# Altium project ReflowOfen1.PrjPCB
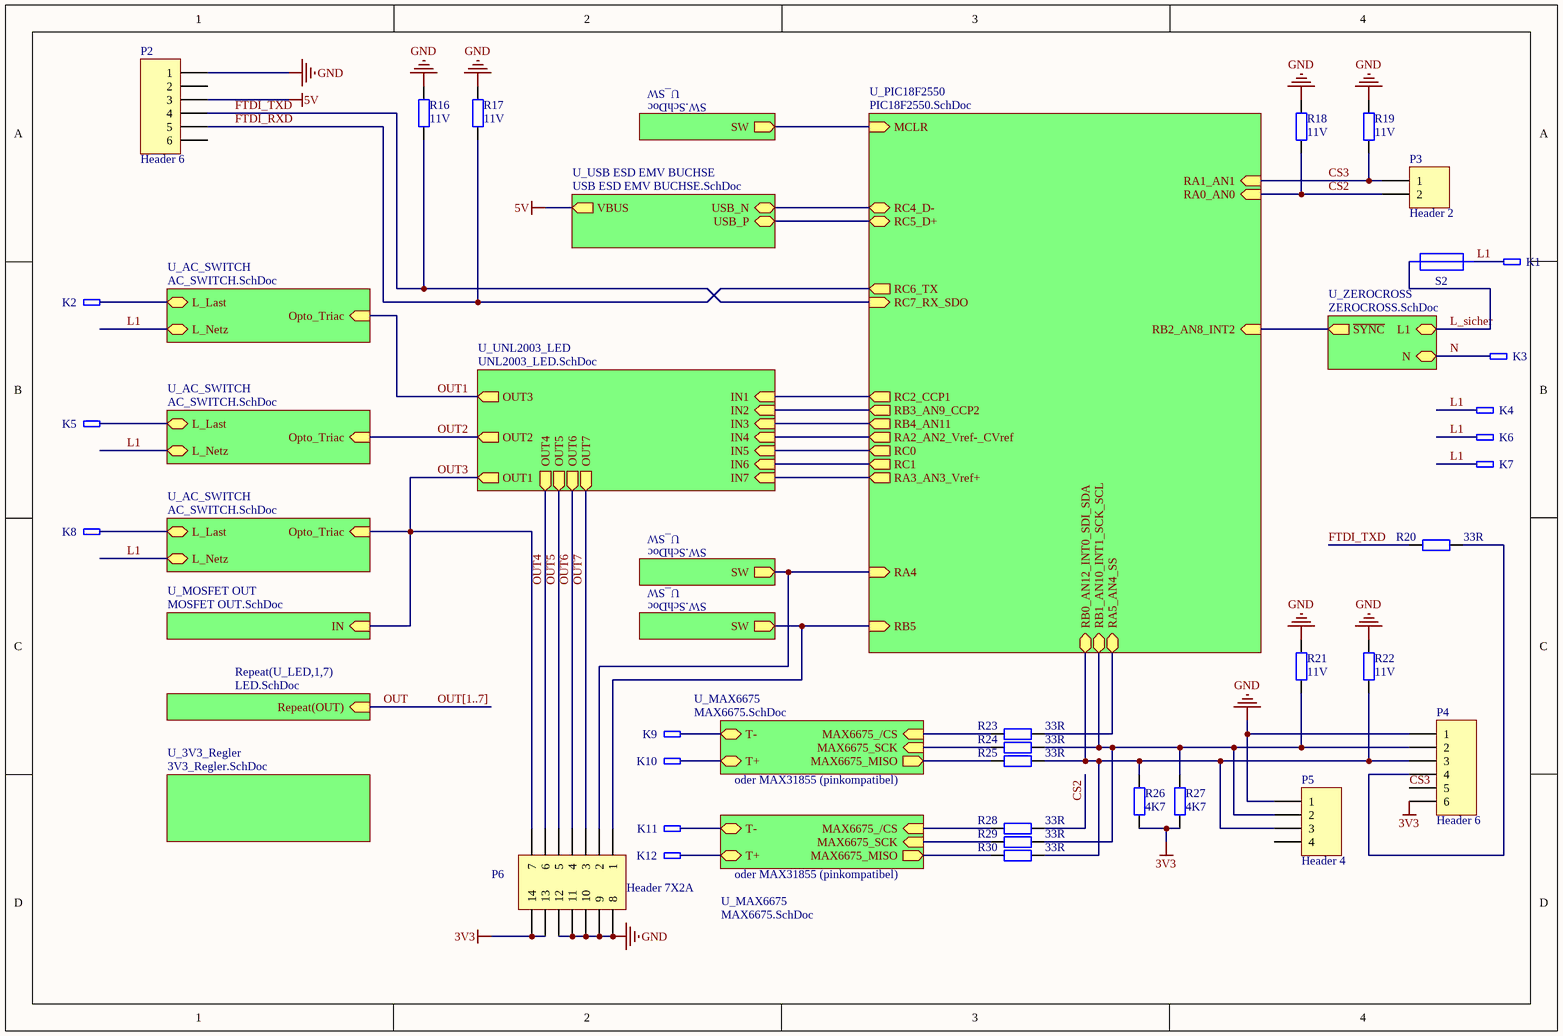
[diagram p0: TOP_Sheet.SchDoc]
11 sheets, 137 parts. Net scope: hierarchical (ports join the sheet entries above them; power ports are global).
Board file: Reflow_1.0.PcbDoc
Sheets:
  TOP_Sheet.SchDoc
    U_3V3_Regler = 3V3_Regler.SchDoc
    U_PIC18F2550 = PIC18F2550.SchDoc
    U_ZEROCROSS = ZEROCROSS.SchDoc
    U_SW = SW.SchDoc
    U_LED1 = LED.SchDoc
    U_LED2 = LED.SchDoc
    U_LED3 = LED.SchDoc
    U_LED4 = LED.SchDoc
    U_LED5 = LED.SchDoc
    U_LED6 = LED.SchDoc
    U_LED7 = LED.SchDoc
    U_MAX6675 = MAX6675.SchDoc
    U_AC_SWITCH = AC_SWITCH.SchDoc
    U_AC_SWITCH = AC_SWITCH.SchDoc
    U_AC_SWITCH = AC_SWITCH.SchDoc
    U_SW = SW.SchDoc
    U_UNL2003_LED = UNL2003_LED.SchDoc
    U_MOSFET OUT = MOSFET OUT.SchDoc
    U_SW = SW.SchDoc
    U_USB ESD EMV BUCHSE = USB ESD EMV BUCHSE.SchDoc
    U_MAX6675 = MAX6675.SchDoc

## Sheet TOP_Sheet.SchDoc
size A4; DocumentNumber: 1; SheetNumber: 1; SheetTotal: 11; Abteilung: Hard/Software Entwicklung

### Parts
K1  WAGO-236  [KL02X196Y0A0]  (value not drawn)
K2  WAGO-236  [KL02X196Y0A0]  (value not drawn)
K3  WAGO-236  [KL02X196Y0A0]  (value not drawn)
K4  WAGO-236  [KL02X196Y0A0]  (value not drawn)
K5  WAGO-236  [KL02X196Y0A0]  (value not drawn)
K6  WAGO-236  [KL02X196Y0A0]  (value not drawn)
K7  WAGO-236  [KL02X196Y0A0]  (value not drawn)
K8  WAGO-236  [KL02X196Y0A0]  (value not drawn)
K9  WAGO-233  [KL02X0Y197A0]  (value not drawn)
K10  WAGO-233  [KL02X0Y197A0]  (value not drawn)
K11  WAGO-233  [KL02X0Y197A0]  (value not drawn)
K12  WAGO-233  [KL02X0Y197A0]  (value not drawn)
P2  Header 6  [HDR1X6]
P3  Header 2  [HDR1X2]
P4  Header 6  [HDR1X6]
P5  Header 4  [HDR1X4]
P6  Header 7X2A  [HDR2X7_CEN]
R16  11V  [RLCDT_1206]
R17  11V  [RLCDT_1206]
R18  11V  [RLCDT_1206]
R19  11V  [RLCDT_1206]
R20  33R  [RLCDT_1206]
R21  11V  [RLCDT_1206]
R22  11V  [RLCDT_1206]
R23  33R  [RLCDT_1206]
R24  33R  [RLCDT_1206]
R25  33R  [RLCDT_1206]
R26  4K7  [RLCDT_1206]
R27  4K7  [RLCDT_1206]
R28  33R  [RLCDT_1206]
R29  33R  [RLCDT_1206]
R30  33R  [RLCDT_1206]
S2  SICHERUNGSHALTER_MIRA  [SICHERUNGSHALTER_MIRA]  (value not drawn)

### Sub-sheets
Repeat(U_LED,1,7) = LED.SchDoc: Repeat(OUT) (in)
U_3V3_Regler = 3V3_Regler.SchDoc: no entries
U_AC_SWITCH = AC_SWITCH.SchDoc: L_Netz (bidir), L_Last (bidir), Opto_Triac (in)
U_AC_SWITCH = AC_SWITCH.SchDoc: L_Netz (bidir), L_Last (bidir), Opto_Triac (in)
U_AC_SWITCH = AC_SWITCH.SchDoc: L_Netz (bidir), L_Last (bidir), Opto_Triac (in)
U_MAX6675 = MAX6675.SchDoc: MAX6675_MISO (out), MAX6675_/CS (in), MAX6675_SCK (in), T+ (bidir), T- (bidir)
U_MAX6675 = MAX6675.SchDoc: MAX6675_MISO (out), MAX6675_/CS (in), MAX6675_SCK (in), T+ (bidir), T- (bidir)
U_MOSFET OUT = MOSFET OUT.SchDoc: IN (in)
U_PIC18F2550 = PIC18F2550.SchDoc: MCLR (in), RA0_AN0 (in), RA1_AN1 (in), RA2_AN2_Vref-_CVref (out), RA3_AN3_Vref+ (out), RA4 (in), RA5_AN4_SS (bidir), RB0_AN12_INT0_SDI_SDA (bidir), RB1_AN10_INT1_SCK_SCL (bidir), RB2_AN8_INT2 (in), RB3_AN9_CCP2 (out), RB4_AN11 (out), RB5 (in), RC0 (out), RC1 (out), RC2_CCP1 (out), RC4_D- (bidir), RC5_D+ (bidir), RC6_TX (out), RC7_RX_SDO (in)
U_SW = SW.SchDoc: SW (out)
U_SW = SW.SchDoc: SW (out)
U_SW = SW.SchDoc: SW (out)
U_UNL2003_LED = UNL2003_LED.SchDoc: IN7 (in), IN6 (in), IN5 (in), IN4 (in), OUT1 (out), OUT2 (out), OUT3 (out), IN1 (in), IN2 (in), IN3 (in), OUT4 (out), OUT5 (out), OUT6 (out), OUT7 (out)
U_USB ESD EMV BUCHSE = USB ESD EMV BUCHSE.SchDoc: USB_N (bidir), USB_P (bidir), VBUS (out)
U_ZEROCROSS = ZEROCROSS.SchDoc: ~{SYNC} (out), L1 (bidir), N (bidir)

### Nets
3V3: P4.6 P6.13 P6.14 R26.2 R27.2
5V: P2.3 ; sheet U_USB ESD EMV BUCHSE/VBUS  [project net VBUS]
GND: P2.1 P4.1 P5.1 P6.8 P6.9 P6.10 P6.11 P6.12 R16.1 R17.1 R18.1 R19.1 R21.1 R22.1
~{SYNC}: sheet U_PIC18F2550/RB2_AN8_INT2, sheet U_ZEROCROSS/~{SYNC}
CS2: P3.2 R18.2 R28.1 ; sheet U_PIC18F2550/RA0_AN0
CS3: P3.1 P4.5 R19.2 ; sheet U_PIC18F2550/RA1_AN1
FTDI_RXD: P2.5 R17.2 ; sheet U_PIC18F2550/RC6_TX
FTDI_TXD: P2.4 R16.2 R20.2 ; sheet U_PIC18F2550/RC7_RX_SDO
L1: K1.1 K4.1 K6.1 K7.1 S2.1 ; sheet U_AC_SWITCH/L_Netz, sheet U_AC_SWITCH/L_Netz, sheet U_AC_SWITCH/L_Netz
L_sicher: S2.4 ; sheet U_ZEROCROSS/L1
MCLR: sheet U_PIC18F2550/MCLR, sheet U_SW/SW
N: K3.1 ; sheet U_ZEROCROSS/N
OUT1: sheet U_AC_SWITCH/Opto_Triac, sheet U_UNL2003_LED/OUT3
OUT2: sheet U_AC_SWITCH/Opto_Triac, sheet U_UNL2003_LED/OUT2
OUT3: P6.7 ; sheet U_AC_SWITCH/Opto_Triac, sheet U_UNL2003_LED/OUT1, sheet U_MOSFET OUT/IN
OUT4: P6.6 ; sheet U_UNL2003_LED/OUT4
OUT5: P6.5 ; sheet U_UNL2003_LED/OUT5
OUT6: P6.4 ; sheet U_UNL2003_LED/OUT6
OUT7: P6.3 ; sheet U_UNL2003_LED/OUT7
USB_N: sheet U_PIC18F2550/RC4_D-, sheet U_USB ESD EMV BUCHSE/USB_N
USB_P: sheet U_PIC18F2550/RC5_D+, sheet U_USB ESD EMV BUCHSE/USB_P
Net*1A_1: K8.1 ; sheet U_AC_SWITCH/L_Last
Net*1B_1: K2.1 ; sheet U_AC_SWITCH/L_Last
Net*1C_1: K5.1 ; sheet U_AC_SWITCH/L_Last
NetC9A_1: K12.1 ; sheet U_MAX6675/T+
NetC9A_2: K11.1 ; sheet U_MAX6675/T-
NetC9B_1: K10.1 ; sheet U_MAX6675/T+
NetC9B_2: K9.1 ; sheet U_MAX6675/T-
NetIC3A_5: R29.2 ; sheet U_MAX6675/MAX6675_SCK
NetIC3A_6: R28.2 ; sheet U_MAX6675/MAX6675_/CS
NetIC3A_7: R30.2 ; sheet U_MAX6675/MAX6675_MISO
NetIC3B_5: R24.2 ; sheet U_MAX6675/MAX6675_SCK
NetIC3B_6: R23.2 ; sheet U_MAX6675/MAX6675_/CS
NetIC3B_7: R25.2 ; sheet U_MAX6675/MAX6675_MISO
NetIC4_1: sheet U_PIC18F2550/RA3_AN3_Vref+, sheet U_UNL2003_LED/IN7
NetIC4_2: sheet U_PIC18F2550/RC1, sheet U_UNL2003_LED/IN6
NetIC4_3: sheet U_PIC18F2550/RC0, sheet U_UNL2003_LED/IN5
NetIC4_4: sheet U_PIC18F2550/RA2_AN2_Vref-_CVref, sheet U_UNL2003_LED/IN4
NetIC4_5: sheet U_PIC18F2550/RC2_CCP1, sheet U_UNL2003_LED/IN1
NetIC4_6: sheet U_PIC18F2550/RB3_AN9_CCP2, sheet U_UNL2003_LED/IN2
NetIC4_7: sheet U_PIC18F2550/RB4_AN11, sheet U_UNL2003_LED/IN3
NetP4_2: P4.2 P5.2 R21.2 R24.1 R27.1 R29.1 ; sheet U_PIC18F2550/RB1_AN10_INT1_SCK_SCL
NetP4_3: P4.3 P5.3 R22.2 R25.1 R26.1 R30.1 ; sheet U_PIC18F2550/RB0_AN12_INT0_SDI_SDA
NetP4_4: P4.4 R20.1
NetP6_1: P6.1 ; sheet U_PIC18F2550/RB5, sheet U_SW/SW
NetP6_2: P6.2 ; sheet U_PIC18F2550/RA4, sheet U_SW/SW
NetR23_1: R23.1 ; sheet U_PIC18F2550/RA5_AN4_SS

Not connected (* = marked no-connect by the designer): P2 2 6; P5 4

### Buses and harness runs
bus OUT[1..7]

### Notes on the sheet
- oder MAX31855 (pinkompatibel)

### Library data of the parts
K1-K8 = WAGO-236: CAGE CLAMP RM5 WAGO236 SERIES; D_Hersteller: WAGO; E_Herstellerbezeichnung: 236
K9-K12 = WAGO-233: CAGE CLAMP RM2.5; B_Bestellnummer: 804769; D_Hersteller: WAGO; E_Herstellerbezeichnung: 233
P2 P4 = Header 6: Header, 6-Pin
P3 = Header 2: Header, 2-Pin
P5 = Header 4: Header, 4-Pin
P6 = Header 7X2A: Header, 7-Pin, Dual row
R16-R19 R21 R22 = R: Widerstand; D_Hersteller: WUERTH; E_Herstellerbezeichnung: 825 41 110
R20 R23-R30 = R: Widerstand
S2 = SICHERUNGSHALTER_MIRA: FUSEHOLDER; B_Bestellnummer: 7851/6

## Sheet 3V3_Regler.SchDoc
size A4; DocumentNumber: 2; SheetNumber: 2; SheetTotal: 11; PageSetup: Record=PageOptions|CenterHorizontal=True|CenterVertical=True|PrintScale=0.70|XCorrection=1.00|YCorrection=1.00|PrintKind=0|BorderSize=5000000|LeftOffset=5|BottomOffset=0|Orientation=1|PaperLength=1000|PaperWidth=1000|Scale=100|PaperSource=7|PrintQuality=-4|MediaType=1|DitherType=10|PaperKind=A4|PrintScaleMode=1; Abteilung: Hard/Software Entwicklung
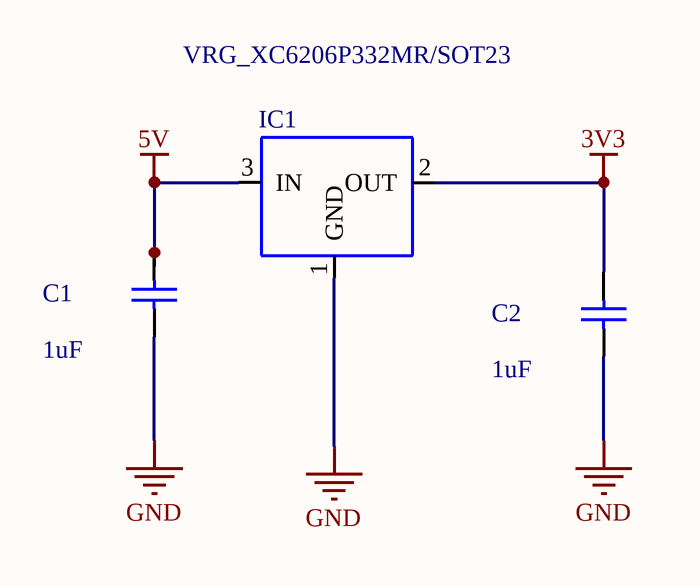
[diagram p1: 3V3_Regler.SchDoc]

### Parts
C1  1uF  [RLCDT_1206]
C2  1uF  [RLCDT_1206]
IC1  VRG_XC6206P332MR/SOT23  [RLCDT_SOT23]

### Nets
3V3: C2.1 IC1.2(OUT)
5V: C1.1 IC1.3(IN)  [project net VBUS]
GND: C1.2 C2.2 IC1.1(GND)

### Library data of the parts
C1 C2 = C_KERAMIK: Kondensator, Keramik
IC1 = VRG_XC6206P332MR/SOT23: VOLTAGE REGULATOR 3V3 250mA; B_Bestellnummer: 58796980; D_Hersteller: TOREX

## Sheet PIC18F2550.SchDoc
size A4; DocumentNumber: 3; SheetNumber: 3; SheetTotal: 11; Abteilung: Hard/Software Entwicklung
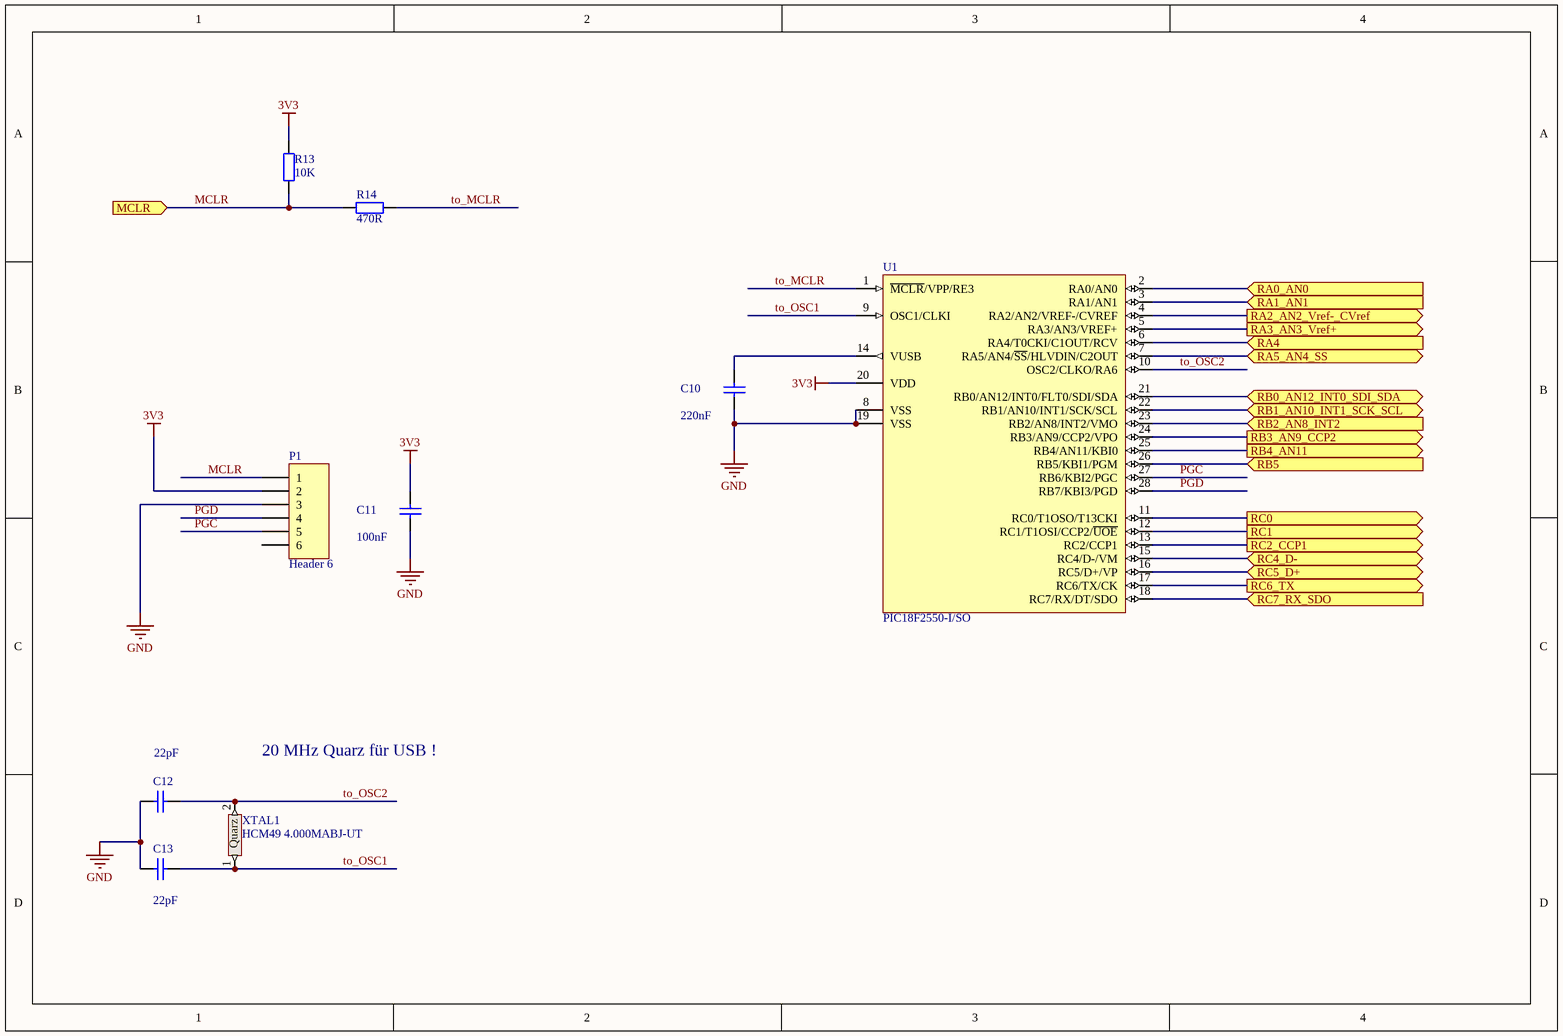
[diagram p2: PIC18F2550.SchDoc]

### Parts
C10  220nF  [RLCDT_1206]
C11  100nF  [RLCDT_1206]
C12  22pF  [RLCDT_1206]
C13  22pF  [RLCDT_1206]
P1  Header 6  [HDR1X6]
R13  10K  [RLCDT_1206]
R14  470R  [RLCDT_1206]
U1  PIC18F2550-I/SO  [SOIC-SO28_N]
XTAL1  HCM49 4.000MABJ-UT  [IC_M-HCM49]

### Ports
MCLR (in), RA0_AN0 (in), RA1_AN1 (in), RA2_AN2_Vref-_CVref (out), RA3_AN3_Vref+ (out), RA4 (in), RA5_AN4_SS (bidir), RB0_AN12_INT0_SDI_SDA (bidir), RB1_AN10_INT1_SCK_SCL (bidir), RB2_AN8_INT2 (in), RB3_AN9_CCP2 (out), RB4_AN11 (out), RB5 (in), RC0 (out), RC1 (out), RC2_CCP1 (out), RC4_D- (bidir), RC5_D+ (bidir), RC6_TX (out), RC7_RX_SDO (in)

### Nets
3V3: C11.1 P1.2 R13.2 U1.20(VDD)
GND: C10.2 C11.2 C12.1 C13.1 P1.3 U1.8(VSS) U1.19(VSS)
~{SYNC}: U1.23(RB2/AN8/INT2/VMO) ; port RB2_AN8_INT2
CS2: U1.2(RA0/AN0) ; port RA0_AN0
CS3: U1.3(RA1/AN1) ; port RA1_AN1
FTDI_RXD: U1.17(RC6/TX/CK) ; port RC6_TX
FTDI_TXD: U1.18(RC7/RX/DT/SDO) ; port RC7_RX_SDO
MCLR: P1.1 R13.1 R14.2 ; port MCLR
PGC: P1.5 U1.27(RB6/KBI2/PGC)
PGD: P1.4 U1.28(RB7/KBI3/PGD)
to_MCLR: R14.1 U1.1(~{MCLR}/VPP/RE3)
to_OSC1: C13.2 U1.9(OSC1/CLKI) XTAL1.1
to_OSC2: C12.2 U1.10(OSC2/CLKO/RA6) XTAL1.2
USB_N: U1.15(RC4/D-/VM) ; port RC4_D-
USB_P: U1.16(RC5/D+/VP) ; port RC5_D+
NetC10_1: C10.1 U1.14(VUSB)
NetIC4_1: U1.5(RA3/AN3/VREF+) ; port RA3_AN3_Vref+
NetIC4_2: U1.12(RC1/T1OSI/CCP2/~{UOE}) ; port RC1
NetIC4_3: U1.11(RC0/T1OSO/T13CKI) ; port RC0
NetIC4_4: U1.4(RA2/AN2/VREF-/CVREF) ; port RA2_AN2_Vref-_CVref
NetIC4_5: U1.13(RC2/CCP1) ; port RC2_CCP1
NetIC4_6: U1.24(RB3/AN9/CCP2/VPO) ; port RB3_AN9_CCP2
NetIC4_7: U1.25(RB4/AN11/KBI0) ; port RB4_AN11
NetP4_2: U1.22(RB1/AN10/INT1/SCK/SCL) ; port RB1_AN10_INT1_SCK_SCL
NetP4_3: U1.21(RB0/AN12/INT0/FLT0/SDI/SDA) ; port RB0_AN12_INT0_SDI_SDA
NetP6_1: U1.26(RB5/KBI1/PGM) ; port RB5
NetP6_2: U1.6(RA4/T0CKI/C1OUT/RCV) ; port RA4
NetR23_1: U1.7(RA5/AN4/~{SS}/HLVDIN/C2OUT) ; port RA5_AN4_SS

Not connected (* = marked no-connect by the designer): P1 6

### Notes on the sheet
- 20 MHz Quarz für USB !

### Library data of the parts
C10-C13 = C_KERAMIK: Kondensator, Keramik
P1 = Header 6: Header, 6-Pin
R13 R14 = R: Widerstand
U1 = PIC18F2550-I/SO: High Performance, Enhanced Flash, USB Microcontroller with nanoWatt Technology, 32K Flash, 28-Pin SOIC, Industrial Temperature Range
XTAL1 = IC_XTAL_4MHz: Quarz 4MHz; B_Bestellnummer: 1611739; D_Hersteller: CITIZEN AMERICA

## Sheet ZEROCROSS.SchDoc
size A4; DocumentNumber: 5; SheetNumber: 5; SheetTotal: 11; PageSetup: Record=PageOptions|CenterHorizontal=True|CenterVertical=True|PrintScale=0.97|XCorrection=1.00|YCorrection=1.00|PrintKind=0|BorderSize=5000000|LeftOffset=5|BottomOffset=0|Orientation=1|PaperLength=1000|PaperWidth=1000|Scale=100|PaperSource=7|PrintQuality=-4|MediaType=1|DitherType=10|PaperKind=A4|PrintScaleMode=1; Abteilung: Hard/Software Entwicklung
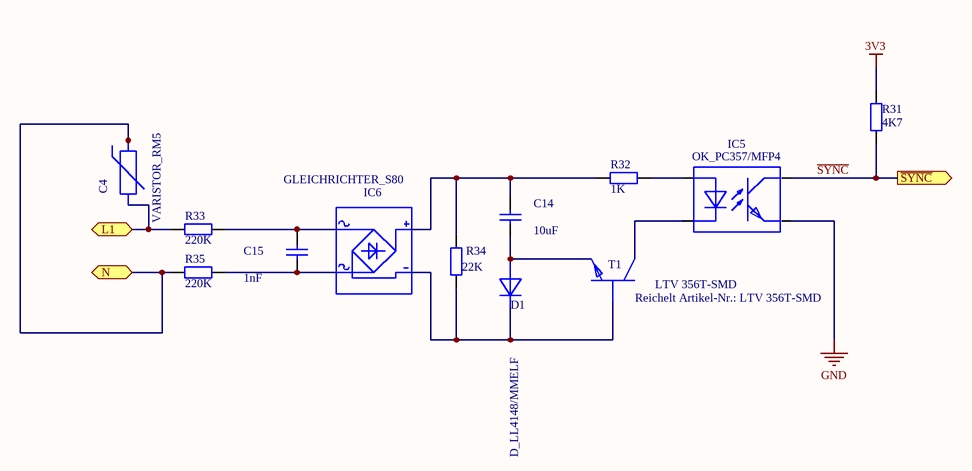
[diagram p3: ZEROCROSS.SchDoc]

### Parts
C4  VARISTOR_RM5  [C02S200E0E28]
C14  10uF  [RLCDT_1206]
C15  1nF  [RLCDT_1206]
D1  D_LL4148/MMELF  [D02X125Y0A0]
IC5  OK_PC357/MFP4  [MFP4]
IC6  GLEICHRICHTER_S80  [DO-269AA]
R31  4K7  [RLCDT_1206]
R32  1K  [RLCDT_1206]
R33  220K  [RLCDT_1206]
R34  22K  [RLCDT_1206]
R35  220K  [RLCDT_1206]
T1  NT_BC847/SOT23  [TR03X80Y95A0]  (value not drawn)

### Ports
L1 (bidir), N (bidir), ~{SYNC} (out)

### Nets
3V3: R31.1
GND: IC5.E
~{SYNC}: IC5.KO R31.2 ; port ~{SYNC}
L_sicher: C4.1 R33.1 ; port L1
N: C4.2 R35.1 ; port N
NetC14_1: C14.1 IC6.1(+) R32.2 R34.2
NetC14_2: C14.2 D1.A T1.E
NetC15_1: C15.1 IC6.3(AC1) R33.2
NetC15_2: C15.2 IC6.4(AC2) R35.2
NetD1_K: D1.K IC6.2(-) R34.1 T1.B
NetIC5_A: IC5.A R32.1
NetIC5_KA: IC5.KA T1.C

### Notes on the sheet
- (near T1) Reichelt Artikel-Nr.: LTV 356T-SMD
- (near T1) LTV 356T-SMD

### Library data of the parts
C4 = VARISTOR_RM5: VARISTOR 275VAC 350VDC RM5 DM7; B_Bestellnummer: 820 57 271  1; D_Hersteller: WUERTH
C14 C15 = C_KERAMIK: Kondensator, Keramik
D1 = D_LL4148/MMELF: B_Bestellnummer: 24 S 3460; E_Herstellerbezeichnung: LL4148
IC5 = OK_PC357/MFP4: B_Bestellnummer: 41084; D_Hersteller: SHARP; E_Herstellerbezeichnung: PC357N3TJ000F
IC6 = GLEICHRICHTER_S80: B_Bestellnummer: 40604; E_Herstellerbezeichnung: S80
R31-R35 = R: Widerstand
T1 = NT_BC847/SOT23: TRANSISTOR NPN SOT23; B_Bestellnummer: 12 S 6268; D_Hersteller: SIEMENS; E_Herstellerbezeichnung: BC847B

## Sheet SW.SchDoc
size A4; DocumentNumber: 7; SheetNumber: 7; SheetTotal: 11; Abteilung: Hard/Software Entwicklung
Used 3 times, as channels U_SW, U_SW, U_SW. Parts and nets are listed once, with the designators drawn on the sheet.
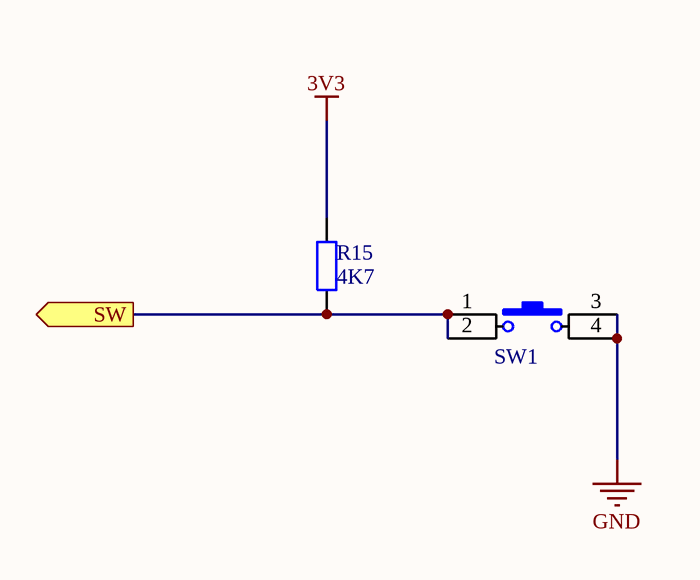
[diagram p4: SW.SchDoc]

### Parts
R15  4K7  [RLCDT_1206]
SW1  Aus Datenbank  [MECH_TASTER_FSM6JSMA]  (value not drawn)

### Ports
SW (out)

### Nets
3V3: R15.2
GND: SW1.3(-) SW1.4(-)
SW: R15.1 SW1.1(-) SW1.2(-) ; port SW

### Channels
U_SW: designators end in C; ports SW=NetP6_2
U_SW: designators end in B; ports SW=NetP6_1
U_SW: designators end in A; ports SW=MCLR

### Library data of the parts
R15 = R: Widerstand
SW1 = MECH_TASTER_FSM6JSMA: SPNO, SMD, 6x6mm, H=3,57mm; D_Hersteller: TYCO ELECTRONICS; B_Bestellnummer: 1555991

## Sheet LED.SchDoc
size A4; DocumentNumber: 9; SheetNumber: 9; SheetTotal: 11; Abteilung: Hard/Software Entwicklung
Used 7 times, as channels U_LED1, U_LED2, U_LED3, U_LED4, U_LED5, U_LED6, U_LED7. Parts and nets are listed once, with the designators drawn on the sheet.
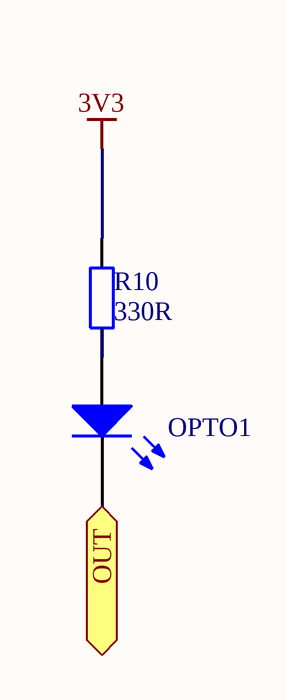
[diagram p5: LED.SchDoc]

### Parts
OPTO1  (no value)  [OPTO_0805_POL]
R10  330R  [RLCDT_1206]

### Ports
OUT (in)

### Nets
3V3: R10.2
OUT: OPTO1.K ; port OUT
NetOPTO1_A: OPTO1.A R10.1

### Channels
U_LED1: designators end in A; ports OUT=OUT1
U_LED2: designators end in B; ports OUT=OUT2
U_LED3: designators end in C; ports OUT=OUT3
U_LED4: designators end in D; ports OUT=OUT4
U_LED5: designators end in E; ports OUT=OUT5
U_LED6: designators end in F; ports OUT=OUT6
U_LED7: designators end in G; ports OUT=OUT7

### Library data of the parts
OPTO1 = OPTO_LED_KP-2012MGC: LED, 0805, mega green
R10 = R: Widerstand

## Sheet MAX6675.SchDoc
size A4; DocumentNumber: 6; SheetNumber: 6; SheetTotal: 11; Abteilung: Hard/Software Entwicklung
Used 2 times, as channels U_MAX6675, U_MAX6675. Parts and nets are listed once, with the designators drawn on the sheet.
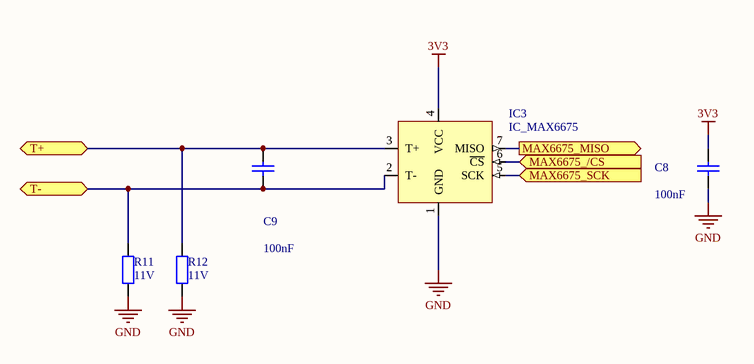
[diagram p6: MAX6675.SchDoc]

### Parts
C8  100nF  [RLCDT_1206]
C9  100nF  [RLCDT_1206]
IC3  IC_MAX6675  [IC_SOIC150_8]
R11  11V  [RLCDT_1206]
R12  11V  [RLCDT_1206]

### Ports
MAX6675_/CS (in), MAX6675_MISO (out), MAX6675_SCK (in), T+ (bidir), T- (bidir)

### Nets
3V3: C8.1 IC3.4(VCC)
GND: C8.2 IC3.1(GND) R11.1 R12.1
MAX6675_/CS: IC3.6(~{CS}) ; port MAX6675_/CS
MAX6675_MISO: IC3.7(MISO) ; port MAX6675_MISO
MAX6675_SCK: IC3.5(SCK) ; port MAX6675_SCK
T+: C9.1 IC3.3(T+) R12.2 ; port T+
T-: C9.2 IC3.2(T-) R11.2 ; port T-

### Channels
U_MAX6675: designators end in B; ports MAX6675_/CS=NetIC3B_6 MAX6675_MISO=NetIC3B_7 MAX6675_SCK=NetIC3B_5 T+=NetC9B_1 T-=NetC9B_2
U_MAX6675: designators end in A; ports MAX6675_/CS=NetIC3A_6 MAX6675_MISO=NetIC3A_7 MAX6675_SCK=NetIC3A_5 T+=NetC9A_1 T-=NetC9A_2

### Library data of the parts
C8 C9 = C_KERAMIK: Kondensator, Keramik
R11 R12 = R: as R16 on sheet TOP_Sheet

## Sheet AC_SWITCH.SchDoc
size A4; DocumentNumber: 10; SheetNumber: 10; SheetTotal: 11; PageSetup: Record=PageOptions|CenterHorizontal=True|CenterVertical=True|PrintScale=0.97|XCorrection=1.00|YCorrection=1.00|PrintKind=0|BorderSize=5000000|LeftOffset=5|BottomOffset=0|Orientation=1|PaperLength=1000|PaperWidth=1000|Scale=100|PaperSource=7|PrintQuality=-4|MediaType=1|DitherType=10|PaperKind=A4|PrintScaleMode=1; Abteilung: Hard/Software Entwicklung
Used 3 times, as channels U_AC_SWITCH, U_AC_SWITCH, U_AC_SWITCH. Parts and nets are listed once, with the designators drawn on the sheet.
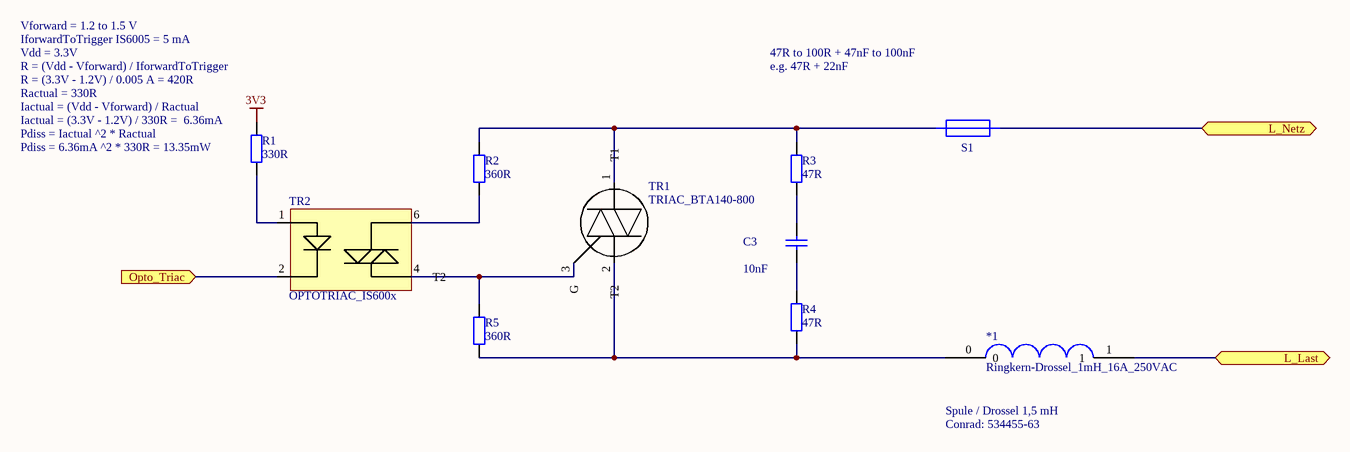
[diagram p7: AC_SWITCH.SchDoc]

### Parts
*1  Ringkern-Drossel_1mH_16A_250VAC  [PCBComponent_1 - duplicate]
C3  10nF  [RLCDT_1206]
R1  330R  [RLCDT_1206]
R2  360R  [RLCDT_1206]
R3  47R  [RLCDT_1206]
R4  47R  [RLCDT_1206]
R5  360R  [RLCDT_1206]
S1  SICHERUNGSHALTER_MIRA  [SICHERUNGSHALTER_MIRA]  (value not drawn)
TR1  TRIAC_BTA140-800  [TO-220]
TR2  OPTOTRIAC_IS600x  [DIP-6]

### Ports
L_Last (bidir), L_Netz (bidir), Opto_Triac (in)

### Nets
3V3: R1.1
L_Last: *1.1 ; port L_Last
L_Netz: S1.1 ; port L_Netz
Opto_Triac: TR2.2(LED_K) ; port Opto_Triac
Net*1_0: *1.0 R4.2 R5.2 TR1.2(T2)
NetC3_1: C3.1 R3.2
NetC3_2: C3.2 R4.1
NetR1_2: R1.2 TR2.1(LED_A)
NetR2_1: R2.1 R3.1 S1.4 TR1.1(T1)
NetR2_2: R2.2 TR2.6(T1)
NetR5_1: R5.1 TR1.3(G) TR2.4(T2)

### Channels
U_AC_SWITCH: designators end in C; ports L_Last=Net*1C_1 L_Netz=L1 Opto_Triac=OUT2
U_AC_SWITCH: designators end in B; ports L_Last=Net*1B_1 L_Netz=L1 Opto_Triac=OUT1
U_AC_SWITCH: designators end in A; ports L_Last=Net*1A_1 L_Netz=L1 Opto_Triac=OUT3

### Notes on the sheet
- Vforward = 1.2 to 1.5 V
- IforwardToTrigger IS6005 = 5 mA
- Vdd = 3.3V
- 47R to 100R + 47nF to 100nF
- R = (Vdd - Vforward) / IforwardToTrigger
- R = (3.3V - 1.2V) / 0.005 A = 420R
- Ractual = 330R
- (near R1) Iactual = (Vdd - Vforward) / Ractual
- (near R1) Iactual = (3.3V - 1.2V) / 330R =  6.36mA
- e.g. 47R + 22nF
- (near R1) Pdiss = 6.36mA ^2 * 330R = 13.35mW
- Pdiss = Iactual ^2 * Ractual
- (near *1) Spule / Drossel 1,5 mH
- Conrad: 534455-63

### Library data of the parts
*1 = Ringkern-Drossel_1mH_16A_250VAC: B_Bestellnummer: 534455-63
C3 = C_KERAMIK: Kondensator, Keramik
R1-R5 = R: Widerstand
S1 = SICHERUNGSHALTER_MIRA: FUSEHOLDER; B_Bestellnummer: 7851/6
TR2 = OPTOTRIAC_IS600x: E_Herstellerbezeichnung: BTA140-800

## Sheet UNL2003_LED.SchDoc
size A4; DocumentNumber: 8; SheetNumber: 8; SheetTotal: 11; Abteilung: Hard/Software Entwicklung
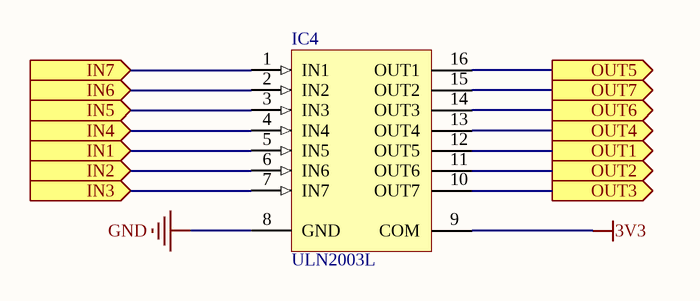
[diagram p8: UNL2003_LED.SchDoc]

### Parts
IC4  ULN2003L  [L16_N]

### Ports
IN1 (in), IN2 (in), IN3 (in), IN4 (in), IN5 (in), IN6 (in), IN7 (in), OUT1 (out), OUT2 (out), OUT3 (out), OUT4 (out), OUT5 (out), OUT6 (out), OUT7 (out)

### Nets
3V3: IC4.9(COM)
GND: IC4.8(GND)
OUT1: IC4.10(OUT7) ; port OUT3
OUT2: IC4.11(OUT6) ; port OUT2
OUT3: IC4.12(OUT5) ; port OUT1
OUT4: IC4.13(OUT4) ; port OUT4
OUT5: IC4.16(OUT1) ; port OUT5
OUT6: IC4.14(OUT3) ; port OUT6
OUT7: IC4.15(OUT2) ; port OUT7
NetIC4_1: IC4.1(IN1) ; port IN7
NetIC4_2: IC4.2(IN2) ; port IN6
NetIC4_3: IC4.3(IN3) ; port IN5
NetIC4_4: IC4.4(IN4) ; port IN4
NetIC4_5: IC4.5(IN5) ; port IN1
NetIC4_6: IC4.6(IN6) ; port IN2
NetIC4_7: IC4.7(IN7) ; port IN3

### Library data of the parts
IC4 = ULN2003L: High-Voltage, High-Current Darlington Array

## Sheet MOSFET OUT.SchDoc
size A4; DocumentNumber: 11; SheetNumber: 11; SheetTotal: 11; PageSetup: Record=PageOptions|CenterHorizontal=True|CenterVertical=True|PrintScale=0.97|XCorrection=1.00|YCorrection=1.00|PrintKind=0|BorderSize=5000000|LeftOffset=5|BottomOffset=0|Orientation=1|PaperLength=1000|PaperWidth=1000|Scale=100|PaperSource=7|PrintQuality=-4|MediaType=1|DitherType=10|PaperKind=A4|PrintScaleMode=1; Abteilung: Hard/Software Entwicklung
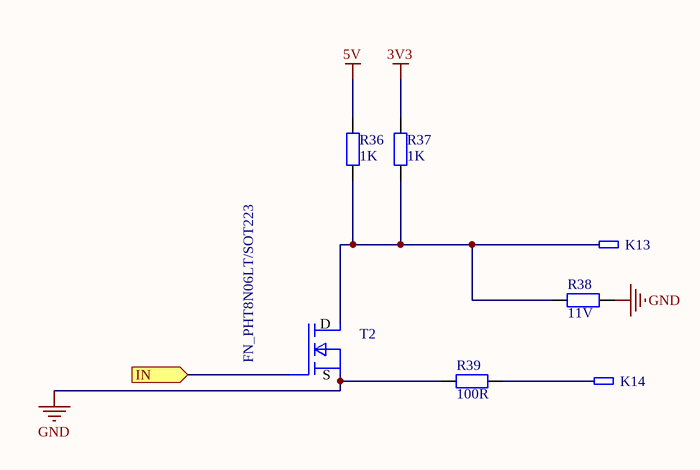
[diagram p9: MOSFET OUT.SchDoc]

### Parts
K13  WAGO-233  [KL02X0Y197A0]  (value not drawn)
K14  WAGO-233  [KL02X0Y197A0]  (value not drawn)
R36  1K  [RLCDT_1206]
R37  1K  [RLCDT_1206]
R38  11V  [RLCDT_1206]
R39  100R  [RLCDT_1206]
T2  FN_PHT8N06LT/SOT223  [SOT223]

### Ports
IN (in)

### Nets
3V3: R37.1
5V: R36.1  [project net VBUS]
GND: R38.1 R39.2 T2.3(S)
OUT3: T2.1(G) ; port IN
NetK13_1: K13.1 R36.2 R37.2 R38.2 T2.2(D)
NetK14_1: K14.1 R39.1

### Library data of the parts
K13 K14 = WAGO-233: as K9 on sheet TOP_Sheet
R36 R37 R39 = R: Widerstand
R38 = R: as R16 on sheet TOP_Sheet
T2 = FN_PHT8N06LT/SOT223: DIGITAL N-CHAN POWER MOSFET 25V 0R6 0A95; B_Bestellnummer: 1081458; D_Hersteller: PHILLIPS

## Sheet USB ESD EMV BUCHSE.SchDoc
size A3; Date: 24.10.2012; CheckedBy: MRipel; Author: Burmeister; Organization: RUETZ TECHNOLOGIES; Address1: Walter-Gropius-Str. 17; Address2: 80807; Address3: München; Address4: Germany; DocumentNumber: 4; Revision: 1.0; SheetNumber: 4; SheetTotal: 11; Abteilung: Hard/Software Entwicklung; Sachnummer: DCB-25863; Datum_V1: 24.10.2012; Version_V1: 1.0; Ersteller_V1: Burmeister; Geprueft_V1: MRipel
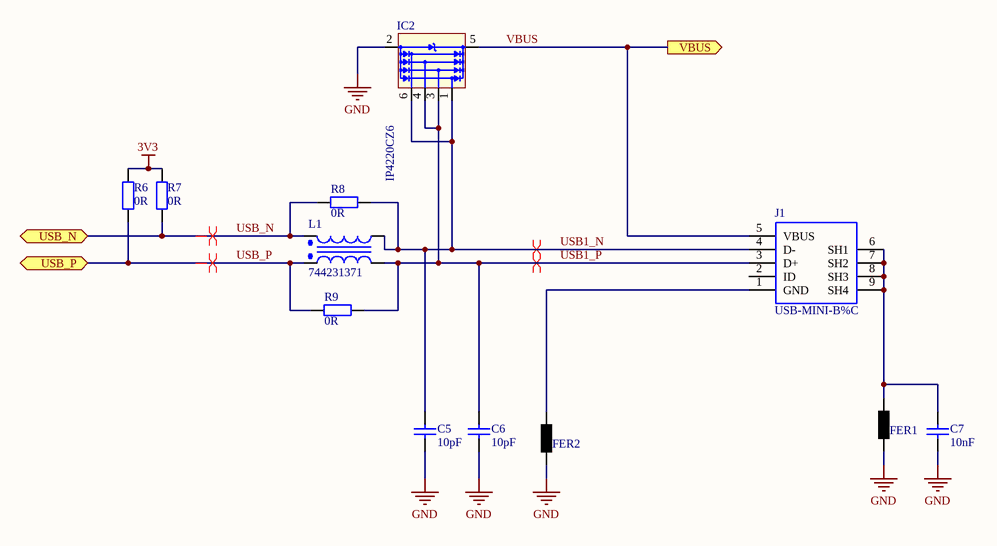
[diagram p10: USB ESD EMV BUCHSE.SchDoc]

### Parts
C5  10pF  [RLCDT_0603]
C6  10pF  [RLCDT_0603]
C7  10nF  [RLCDT_0603]
FER1  742792651  [RLCDT_0603]  (value not drawn)
FER2  742792651  [RLCDT_0603]  (value not drawn)
IC2  IP4220CZ6  [ESD_SOT457]
J1  USB-MINI-B%C  [USB-MINI-B_2]
L1  744231371  [RLCDT_CMC_WÜRTH_CNSW_0805]
R6  0R  [RLCDT_1206]
R7  0R  [RLCDT_1206]
R8  0R  [RLCDT_0603]
R9  0R  [RLCDT_0603]

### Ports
USB_N (bidir), USB_P (bidir), VBUS (out)

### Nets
3V3: R6.1 R7.1
GND: C5.1 C6.1 C7.2 FER1.1 FER2.2 IC2.2(GND)
VBUS: IC2.5(Vp) J1.5(VBUS) ; port VBUS
USB1_N: C5.2 IC2.1(I/O_1) IC2.6(I/O_4) J1.4(D-) L1.2 R8.1
USB1_P: C6.2 IC2.3(I/O_2) IC2.4(I/O_3) J1.3(D+) L1.3 R9.1
USB_N: L1.1 R7.2 R8.2 ; port USB_N
USB_P: L1.4 R6.2 R9.2 ; port USB_P
NetC7_1: C7.1 FER1.2 J1.6(SH1) J1.7(SH2) J1.8(SH3) J1.9(SH4)
NetFER2_1: FER2.1 J1.1(GND)

Not connected (* = marked no-connect by the designer): J1 2(ID)

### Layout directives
differential pair: USB1_N, USB1_P, USB_N, USB_P

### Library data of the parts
C5 C6 = C_KERAMIK: Kondensator, Keramik; D_Hersteller: AVX; E_Herstellerbezeichnung: 06035A100JAT2A; B_Bestellnummer: 499110RL
C7 = C_KERAMIK: Kondensator, Keramik; D_Hersteller: KEMET; E_Herstellerbezeichnung: C0603C103K5RAC; B_Bestellnummer: 1414609
FER1 FER2 = FER: Ferrit; D_Hersteller: Würth Elektronik
IC2 = ESD_IP4220CZ6: ESD, USB, level4, 8kV; B_Bestellnummer: 1506629; D_Hersteller: NXP
L1 = L_CMC: Common Mode Choke, Spule; D_Hersteller: Würth Elektronik
R6-R9 = R: Widerstand

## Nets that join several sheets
3V3: TOP_Sheet (5 pins), 3V3_Regler (C2.1 IC1.2), PIC18F2550 (C11.1 P1.2 R13.2 U1.20), ZEROCROSS (R31.1), U_SW (R15C.2), U_LED1 (R10A.2), U_LED2 (R10B.2), U_LED3 (R10C.2), U_LED4 (R10D.2), U_LED5 (R10E.2), U_LED6 (R10F.2), U_LED7 (R10G.2), U_MAX6675 (C8B.1 IC3B.4), U_AC_SWITCH (R1C.1), U_AC_SWITCH (R1B.1), U_AC_SWITCH (R1A.1), U_SW (R15B.2), UNL2003_LED (IC4.9), MOSFET OUT (R37.1), U_SW (R15A.2), USB ESD EMV BUCHSE (R6.1 R7.1), U_MAX6675 (C8A.1 IC3A.4)
GND: TOP_Sheet (14 pins), 3V3_Regler (C1.2 C2.2 IC1.1), PIC18F2550 (7 pins), ZEROCROSS (IC5.E), U_SW (SW1C.3 SW1C.4), U_MAX6675 (C8B.2 IC3B.1 R11B.1 R12B.1), U_SW (SW1B.3 SW1B.4), UNL2003_LED (IC4.8), MOSFET OUT (R38.1 R39.2 T2.3), U_SW (SW1A.3 SW1A.4), USB ESD EMV BUCHSE (6 pins), U_MAX6675 (C8A.2 IC3A.1 R11A.1 R12A.1)
VBUS: TOP_Sheet (P2.3), 3V3_Regler (C1.1 IC1.3), MOSFET OUT (R36.1), USB ESD EMV BUCHSE (IC2.5 J1.5)
~{SYNC}: PIC18F2550 (U1.23), ZEROCROSS (IC5.KO R31.2)
CS2: TOP_Sheet (P3.2 R18.2 R28.1), PIC18F2550 (U1.2)
CS3: TOP_Sheet (P3.1 P4.5 R19.2), PIC18F2550 (U1.3)
FTDI_RXD: TOP_Sheet (P2.5 R17.2), PIC18F2550 (U1.17)
FTDI_TXD: TOP_Sheet (P2.4 R16.2 R20.2), PIC18F2550 (U1.18)
L1: TOP_Sheet (5 pins), U_AC_SWITCH (S1C.1), U_AC_SWITCH (S1B.1), U_AC_SWITCH (S1A.1)
L_sicher: TOP_Sheet (S2.4), ZEROCROSS (C4.1 R33.1)
MCLR: PIC18F2550 (P1.1 R13.1 R14.2), U_SW (R15A.1 SW1A.1 SW1A.2)
N: TOP_Sheet (K3.1), ZEROCROSS (C4.2 R35.1)
Net*1A_1: TOP_Sheet (K8.1), U_AC_SWITCH (*1A.1)
Net*1B_1: TOP_Sheet (K2.1), U_AC_SWITCH (*1B.1)
Net*1C_1: TOP_Sheet (K5.1), U_AC_SWITCH (*1C.1)
NetC9A_1: TOP_Sheet (K12.1), U_MAX6675 (C9A.1 IC3A.3 R12A.2)
NetC9A_2: TOP_Sheet (K11.1), U_MAX6675 (C9A.2 IC3A.2 R11A.2)
NetC9B_1: TOP_Sheet (K10.1), U_MAX6675 (C9B.1 IC3B.3 R12B.2)
NetC9B_2: TOP_Sheet (K9.1), U_MAX6675 (C9B.2 IC3B.2 R11B.2)
NetIC3A_5: TOP_Sheet (R29.2), U_MAX6675 (IC3A.5)
NetIC3A_6: TOP_Sheet (R28.2), U_MAX6675 (IC3A.6)
NetIC3A_7: TOP_Sheet (R30.2), U_MAX6675 (IC3A.7)
NetIC3B_5: TOP_Sheet (R24.2), U_MAX6675 (IC3B.5)
NetIC3B_6: TOP_Sheet (R23.2), U_MAX6675 (IC3B.6)
NetIC3B_7: TOP_Sheet (R25.2), U_MAX6675 (IC3B.7)
NetIC4_1: PIC18F2550 (U1.5), UNL2003_LED (IC4.1)
NetIC4_2: PIC18F2550 (U1.12), UNL2003_LED (IC4.2)
NetIC4_3: PIC18F2550 (U1.11), UNL2003_LED (IC4.3)
NetIC4_4: PIC18F2550 (U1.4), UNL2003_LED (IC4.4)
NetIC4_5: PIC18F2550 (U1.13), UNL2003_LED (IC4.5)
NetIC4_6: PIC18F2550 (U1.24), UNL2003_LED (IC4.6)
NetIC4_7: PIC18F2550 (U1.25), UNL2003_LED (IC4.7)
NetP4_2: TOP_Sheet (6 pins), PIC18F2550 (U1.22)
NetP4_3: TOP_Sheet (6 pins), PIC18F2550 (U1.21)
NetP6_1: TOP_Sheet (P6.1), PIC18F2550 (U1.26), U_SW (R15B.1 SW1B.1 SW1B.2)
NetP6_2: TOP_Sheet (P6.2), PIC18F2550 (U1.6), U_SW (R15C.1 SW1C.1 SW1C.2)
NetR23_1: TOP_Sheet (R23.1), PIC18F2550 (U1.7)
OUT1: U_LED1 (OPTO1A.K), U_AC_SWITCH (TR2B.2), UNL2003_LED (IC4.10)
OUT2: U_LED2 (OPTO1B.K), U_AC_SWITCH (TR2C.2), UNL2003_LED (IC4.11)
OUT3: TOP_Sheet (P6.7), U_LED3 (OPTO1C.K), U_AC_SWITCH (TR2A.2), UNL2003_LED (IC4.12), MOSFET OUT (T2.1)
OUT4: TOP_Sheet (P6.6), U_LED4 (OPTO1D.K), UNL2003_LED (IC4.13)
OUT5: TOP_Sheet (P6.5), U_LED5 (OPTO1E.K), UNL2003_LED (IC4.16)
OUT6: TOP_Sheet (P6.4), U_LED6 (OPTO1F.K), UNL2003_LED (IC4.14)
OUT7: TOP_Sheet (P6.3), U_LED7 (OPTO1G.K), UNL2003_LED (IC4.15)
USB_N: PIC18F2550 (U1.15), USB ESD EMV BUCHSE (L1.1 R7.2 R8.2)
USB_P: PIC18F2550 (U1.16), USB ESD EMV BUCHSE (L1.4 R6.2 R9.2)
